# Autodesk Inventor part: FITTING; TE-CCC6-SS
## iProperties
Title: FITTING; TE-CCC6-SS
Author: JT
Created: 2001-12
Part Number: CCC6-SS
Material: Stainless Steel, 440C
Description: FITTING; TE-CCC6-SS
Vendor: Aeroquip
Document SubType Name: Modeling
Designer: JT
MODEL - 1: ---
MODEL - 2: ---
RAW MATERIAL: --------
SCALE:: 1=??
SIZE: 00 x 00 x 00
SUB-ASSY - 1: ------
SUB-ASSY - 1 - QUA: 1
SUB-ASSY - 2: ------
SUB-ASSY - 2 - QUA: 1
SYM. TO:: N/A
TEMPLATE CREATION: -- / __-__-__
Control State: 0
Master: False
Checked Out: False
Last Check In By: Jefft
Last Check In Date: 2001-12-07
PropertySet Name: Design Tracking Control
Shininess: 54.0
Length Units: 11272
Angle Units: 11286
Time Units: 11279
Mass Units: 11290
Length Display Precision: 3
Angle Display Precision: 2
Compacted: True
PropertySet Name: _Private Model Information
Density: 0.0
Volumn: 0.0
Area: 0.0
PropertySet Name: Model Information
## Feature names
1. Extrusion2
2. Body_Chamfer [Revolution]
3. Edge Relief [Fillet]
4. Male1_Jic1 [Revolution]
5. male1 Thru Hole [Extrusion]
6. Male1_Fillet [Fillet]
7. Male_2Jic2 [Revolution]
8. male2 Thru Hole [Extrusion]
9. Male2_Fillet2 [Fillet]
10. Female1_Revolve1 [Revolution]
11. Female1_Hex [Extrusion]
12. Femal1_Hexnut taper [Revolution]
13. male3_Jic3 [Revolution]
14. male3_Fillet3 [Fillet]
15. male3 Thru Hole [Extrusion]
16. Female2_Revolve2 [Revolution]
17. Female2_Hex [Extrusion]
18. Femal2_Hexnut Taper [Revolution]
19. Female2 Thru Hole [Extrusion]
